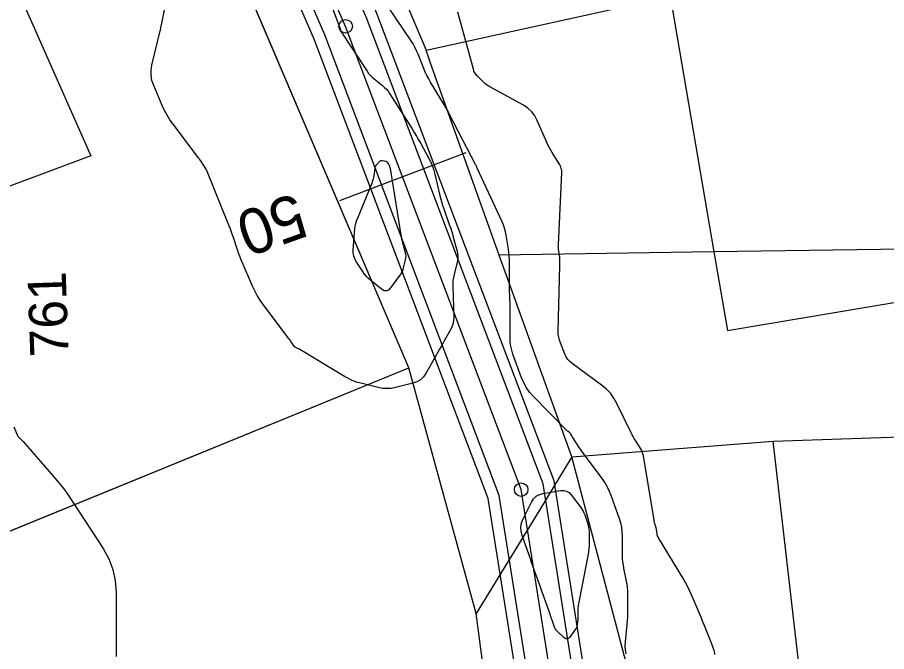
# Model space of a CAD drawing. Extents: x -534481 to -534256, y -1190577 to -1190138.
# Drawn here: x -534403.93 to -534384.66, y -1190491.61 to -1190477.55 of the extents above; entities that cross this region are included whole.
import ezdxf

# ---------------------------------------------------------------- set-up
doc = ezdxf.new("R2010")
doc.units = 0
for name, color, linetype in [('0_kroužky', 7, 'Continuous'), ('30', 7, 'Continuous'), ('31', 7, 'Continuous'), ('_N_osa', 7, 'Continuous'), ('_N_text', 7, 'Continuous'), ('_tenka', 7, 'Continuous'), ('Hranice parcel', 7, 'Continuous'), ('Parcelní čísla', 7, 'Continuous'), ('Polygon budovy', 7, 'Continuous')]:
    doc.layers.add(name, color=color, linetype=linetype)

msp = doc.modelspace()

# ---------------------------------------------------------------- linework, layer by layer
at = {"layer": '0_kroužky'}
for centre in [(-534396.655, -1190477.752), (-534396.655, -1190477.752), (-534396.655, -1190477.752), (-534396.655, -1190477.752), (-534396.655, -1190477.752), (-534396.655, -1190477.752), (-534392.763, -1190488.017), (-534392.763, -1190488.017), (-534392.763, -1190488.017), (-534392.763, -1190488.017), (-534392.763, -1190488.017), (-534392.763, -1190488.017)]:
    msp.add_circle(centre, 0.15, dxfattribs=at)
at = {"layer": '30'}
for points in [[(-534390.433, -1190491.658), (-534390.451, -1190491.57), (-534390.457, -1190491.482), (-534390.453, -1190491.391), (-534390.414, -1190491.008), (-534390.406, -1190490.926), (-534390.401, -1190490.844), (-534390.398, -1190490.762), (-534390.398, -1190490.68), (-534390.4, -1190490.333), (-534390.402, -1190490.26), (-534390.407, -1190490.188), (-534390.417, -1190490.116), (-534390.429, -1190490.045), (-534390.487, -1190489.759), (-534390.499, -1190489.688), (-534390.508, -1190489.616), (-534390.514, -1190489.544), (-534390.516, -1190489.471), (-534390.518, -1190489.038), (-534390.522, -1190488.942), (-534390.534, -1190488.847), (-534390.555, -1190488.754), (-534390.583, -1190488.663), (-534390.76, -1190488.167), (-534390.804, -1190488.057), (-534390.856, -1190487.95), (-534390.916, -1190487.848), (-534390.984, -1190487.75), (-534391.37, -1190487.236), (-534391.398, -1190487.198), (-534391.426, -1190487.16), (-534391.452, -1190487.121), (-534391.478, -1190487.082), (-534391.621, -1190486.862), (-534391.626, -1190486.853), (-534391.632, -1190486.844), (-534391.636, -1190486.835), (-534391.641, -1190486.826), (-534391.659, -1190486.788), (-534391.664, -1190486.779), (-534391.67, -1190486.771), (-534391.677, -1190486.764), (-534391.685, -1190486.757), (-534391.724, -1190486.729), (-534391.734, -1190486.722), (-534391.742, -1190486.714), (-534391.751, -1190486.707), (-534391.759, -1190486.699), (-534392.498, -1190485.948), (-534392.579, -1190485.857), (-534392.649, -1190485.758), (-534392.708, -1190485.653), (-534392.755, -1190485.54), (-534392.946, -1190485.017), (-534392.973, -1190484.93), (-534392.993, -1190484.842), (-534393.005, -1190484.752), (-534393.009, -1190484.661), (-534393.009, -1190484.246), (-534393.009, -1190484.178), (-534393.009, -1190484.11), (-534393.01, -1190484.042), (-534393.011, -1190483.974), (-534393.017, -1190483.703), (-534393.019, -1190483.635), (-534393.02, -1190483.567), (-534393.02, -1190483.499), (-534393.02, -1190483.432), (-534393.02, -1190483.002), (-534393.022, -1190482.923), (-534393.027, -1190482.845), (-534393.034, -1190482.767), (-534393.046, -1190482.689), (-534393.097, -1190482.379), (-534393.112, -1190482.302), (-534393.133, -1190482.227), (-534393.158, -1190482.153), (-534393.188, -1190482.081), (-534393.739, -1190480.892), (-534393.743, -1190480.882), (-534393.746, -1190480.873), (-534393.753, -1190480.852), (-534393.756, -1190480.845), (-534393.759, -1190480.838), (-534393.77, -1190480.818), (-534393.773, -1190480.811), (-534394.342, -1190479.717), (-534394.389, -1190479.627), (-534394.438, -1190479.538), (-534394.489, -1190479.45), (-534394.541, -1190479.363), (-534394.77, -1190478.99), (-534394.813, -1190478.916), (-534394.853, -1190478.841), (-534394.889, -1190478.765), (-534394.922, -1190478.686), (-534395.047, -1190478.37), (-534395.081, -1190478.292), (-534395.118, -1190478.216), (-534395.16, -1190478.142), (-534395.205, -1190478.07), (-534395.7, -1190477.339)], [(-534404.007, -1190486.624), (-534403.927, -1190486.816), (-534403.921, -1190486.83), (-534403.913, -1190486.842), (-534403.904, -1190486.854), (-534403.893, -1190486.865), (-534403.847, -1190486.905), (-534403.835, -1190486.915), (-534403.824, -1190486.926), (-534403.814, -1190486.937), (-534403.803, -1190486.948), (-534403.126, -1190487.727), (-534403.012, -1190487.863), (-534402.903, -1190488.002), (-534402.799, -1190488.145), (-534402.7, -1190488.292), (-534402.031, -1190489.324), (-534401.905, -1190489.551), (-534401.815, -1190489.788), (-534401.761, -1190490.036), (-534401.743, -1190490.295), (-534401.743, -1190491.711)]]:
    msp.add_lwpolyline(points, dxfattribs=at)
msp.add_lwpolyline([(-534395.702, -1190483.595), (-534395.75, -1190483.615), (-534395.802, -1190483.609), (-534395.857, -1190483.576), (-534396.094, -1190483.386), (-534396.145, -1190483.342), (-534396.192, -1190483.294), (-534396.235, -1190483.242), (-534396.274, -1190483.187), (-534396.421, -1190482.959), (-534396.453, -1190482.9), (-534396.474, -1190482.839), (-534396.485, -1190482.775), (-534396.486, -1190482.709), (-534396.459, -1190482.317), (-534396.45, -1190482.229), (-534396.433, -1190482.144), (-534396.41, -1190482.06), (-534396.38, -1190481.977), (-534396.061, -1190481.202), (-534396.048, -1190481.168), (-534396.038, -1190481.133), (-534396.029, -1190481.098), (-534396.023, -1190481.062), (-534396.001, -1190480.889), (-534395.996, -1190480.867), (-534395.988, -1190480.848), (-534395.978, -1190480.829), (-534395.964, -1190480.813), (-534395.893, -1190480.741), (-534395.881, -1190480.731), (-534395.868, -1190480.725), (-534395.854, -1190480.722), (-534395.838, -1190480.724), (-534395.761, -1190480.739), (-534395.753, -1190480.741), (-534395.745, -1190480.745), (-534395.739, -1190480.751), (-534395.733, -1190480.758), (-534395.709, -1190480.795), (-534395.704, -1190480.805), (-534395.698, -1190480.815), (-534395.687, -1190480.835), (-534395.685, -1190480.84), (-534395.682, -1190480.845), (-534395.68, -1190480.85), (-534395.679, -1190480.856), (-534395.668, -1190480.905), (-534395.665, -1190480.915), (-534395.663, -1190480.925), (-534395.661, -1190480.935), (-534395.66, -1190480.945), (-534395.42, -1190482.421), (-534395.413, -1190482.464), (-534395.404, -1190482.507), (-534395.394, -1190482.55), (-534395.382, -1190482.592), (-534395.335, -1190482.76), (-534395.326, -1190482.802), (-534395.322, -1190482.845), (-534395.325, -1190482.887), (-534395.332, -1190482.929), (-534395.376, -1190483.103), (-534395.389, -1190483.146), (-534395.405, -1190483.186), (-534395.426, -1190483.225), (-534395.45, -1190483.262), (-534395.657, -1190483.549)], close=True, dxfattribs=at)
at = {"layer": '31'}
for points in [[(-534397.096, -1190476.95), (-534396.777, -1190477.804), (-534396.774, -1190477.81), (-534396.773, -1190477.816), (-534396.771, -1190477.821), (-534396.77, -1190477.828), (-534396.765, -1190477.852), (-534396.763, -1190477.858), (-534396.761, -1190477.863), (-534396.759, -1190477.869), (-534396.756, -1190477.874), (-534396.178, -1190478.746), (-534396.144, -1190478.794), (-534396.106, -1190478.838), (-534396.065, -1190478.88), (-534396.021, -1190478.918), (-534395.836, -1190479.065), (-534395.791, -1190479.104), (-534395.75, -1190479.145), (-534395.713, -1190479.19), (-534395.68, -1190479.239), (-534395.181, -1190480.022), (-534395.132, -1190480.102), (-534395.083, -1190480.183), (-534395.036, -1190480.265), (-534394.99, -1190480.347), (-534394.809, -1190480.679), (-534394.767, -1190480.763), (-534394.73, -1190480.849), (-534394.7, -1190480.938), (-534394.675, -1190481.028), (-534394.572, -1190481.469), (-534394.552, -1190481.552), (-534394.529, -1190481.634), (-534394.504, -1190481.715), (-534394.477, -1190481.796), (-534394.357, -1190482.14), (-534394.333, -1190482.21), (-534394.311, -1190482.28), (-534394.289, -1190482.35), (-534394.269, -1190482.42), (-534394.187, -1190482.71), (-534394.173, -1190482.777), (-534394.167, -1190482.845), (-534394.171, -1190482.912), (-534394.183, -1190482.98), (-534394.251, -1190483.251), (-534394.266, -1190483.319), (-534394.275, -1190483.387), (-534394.28, -1190483.456), (-534394.281, -1190483.526), (-534394.259, -1190484.187), (-534394.262, -1190484.259), (-534394.274, -1190484.328), (-534394.295, -1190484.396), (-534394.326, -1190484.461), (-534394.468, -1190484.717), (-534394.503, -1190484.781), (-534394.539, -1190484.844), (-534394.575, -1190484.908), (-534394.611, -1190484.972), (-534394.876, -1190485.441), (-534394.931, -1190485.52), (-534394.998, -1190485.582), (-534395.076, -1190485.63), (-534395.166, -1190485.661), (-534395.551, -1190485.756), (-534395.647, -1190485.774), (-534395.743, -1190485.78), (-534395.839, -1190485.774), (-534395.935, -1190485.756), (-534396.319, -1190485.66), (-534396.414, -1190485.633), (-534396.506, -1190485.599), (-534396.594, -1190485.558), (-534396.681, -1190485.51), (-534397.67, -1190484.912), (-534397.677, -1190484.908), (-534397.684, -1190484.904), (-534397.691, -1190484.901), (-534397.699, -1190484.897), (-534397.738, -1190484.88), (-534397.746, -1190484.876), (-534397.759, -1190484.869), (-534397.764, -1190484.865), (-534397.769, -1190484.862), (-534397.784, -1190484.85), (-534397.787, -1190484.847), (-534397.789, -1190484.844), (-534397.792, -1190484.841), (-534397.795, -1190484.838), (-534397.866, -1190484.734), (-534397.878, -1190484.715), (-534397.891, -1190484.697), (-534397.905, -1190484.679), (-534397.918, -1190484.661), (-534398.48, -1190483.918), (-534398.549, -1190483.82), (-534398.612, -1190483.719), (-534398.669, -1190483.614), (-534398.72, -1190483.506), (-534398.946, -1190482.979), (-534398.974, -1190482.911), (-534399.001, -1190482.843), (-534399.026, -1190482.775), (-534399.05, -1190482.706), (-534399.143, -1190482.429), (-534399.167, -1190482.36), (-534399.191, -1190482.291), (-534399.217, -1190482.223), (-534399.244, -1190482.155), (-534399.738, -1190480.933), (-534399.741, -1190480.927), (-534399.744, -1190480.921), (-534399.747, -1190480.915), (-534399.75, -1190480.909), (-534399.774, -1190480.87), (-534399.787, -1190480.848), (-534399.794, -1190480.838), (-534399.865, -1190480.734), (-534399.878, -1190480.716), (-534399.89, -1190480.698), (-534399.904, -1190480.68), (-534399.917, -1190480.662), (-534400.48, -1190479.918), (-534400.549, -1190479.82), (-534400.612, -1190479.719), (-534400.669, -1190479.614), (-534400.72, -1190479.506), (-534400.909, -1190479.065), (-534400.947, -1190478.954), (-534400.966, -1190478.841), (-534400.966, -1190478.727), (-534400.947, -1190478.611), (-534400.771, -1190477.88), (-534400.769, -1190477.87), (-534400.766, -1190477.86), (-534400.76, -1190477.841), (-534400.757, -1190477.831), (-534400.755, -1190477.821), (-534400.589, -1190476.994)], [(-534388.464, -1190491.668), (-534388.488, -1190491.585), (-534388.515, -1190491.502), (-534388.546, -1190491.421), (-534388.708, -1190491.015), (-534388.742, -1190490.93), (-534388.777, -1190490.845), (-534388.813, -1190490.76), (-534388.849, -1190490.675), (-534388.994, -1190490.337), (-534389.031, -1190490.253), (-534389.072, -1190490.17), (-534389.115, -1190490.089), (-534389.161, -1190490.01), (-534389.717, -1190489.087), (-534389.729, -1190489.065), (-534389.739, -1190489.042), (-534389.746, -1190489.018), (-534389.751, -1190488.994), (-534389.774, -1190488.858), (-534389.776, -1190488.851), (-534389.777, -1190488.845), (-534389.779, -1190488.838), (-534389.781, -1190488.831), (-534389.791, -1190488.805), (-534389.793, -1190488.799), (-534389.795, -1190488.792), (-534389.796, -1190488.786), (-534389.798, -1190488.779), (-534390.054, -1190487.268), (-534390.065, -1190487.221), (-534390.08, -1190487.176), (-534390.1, -1190487.132), (-534390.124, -1190487.09), (-534390.23, -1190486.926), (-534390.256, -1190486.885), (-534390.281, -1190486.843), (-534390.304, -1190486.8), (-534390.326, -1190486.757), (-534390.64, -1190486.106), (-534390.706, -1190485.989), (-534390.784, -1190485.882), (-534390.876, -1190485.785), (-534390.98, -1190485.699), (-534391.634, -1190485.223), (-534391.685, -1190485.18), (-534391.728, -1190485.132), (-534391.765, -1190485.078), (-534391.794, -1190485.018), (-534391.895, -1190484.768), (-534391.917, -1190484.704), (-534391.932, -1190484.64), (-534391.94, -1190484.574), (-534391.942, -1190484.507), (-534391.91, -1190483.052), (-534391.909, -1190483.031), (-534391.909, -1190483.01), (-534391.909, -1190482.99), (-534391.909, -1190482.969), (-534391.909, -1190482.886), (-534391.909, -1190482.865), (-534391.911, -1190482.845), (-534391.913, -1190482.824), (-534391.916, -1190482.804), (-534391.933, -1190482.696), (-534391.937, -1190482.671), (-534391.939, -1190482.646), (-534391.94, -1190482.621), (-534391.939, -1190482.596), (-534391.861, -1190480.991), (-534391.861, -1190480.976), (-534391.862, -1190480.961), (-534391.864, -1190480.947), (-534391.868, -1190480.932), (-534391.884, -1190480.874), (-534391.889, -1190480.859), (-534391.894, -1190480.845), (-534391.901, -1190480.832), (-534391.908, -1190480.819), (-534392.079, -1190480.546), (-534392.109, -1190480.496), (-534392.137, -1190480.445), (-534392.164, -1190480.392), (-534392.188, -1190480.339), (-534392.417, -1190479.82), (-534392.47, -1190479.722), (-534392.536, -1190479.636), (-534392.616, -1190479.562), (-534392.71, -1190479.501), (-534393.456, -1190479.094), (-534393.496, -1190479.071), (-534393.534, -1190479.045), (-534393.569, -1190479.016), (-534393.603, -1190478.985), (-534393.734, -1190478.854), (-534393.764, -1190478.82), (-534393.789, -1190478.783), (-534393.809, -1190478.743), (-534393.823, -1190478.7), (-534394.17, -1190477.437)]]:
    msp.add_lwpolyline(points, dxfattribs=at)
msp.add_lwpolyline([(-534391.717, -1190491.319), (-534391.746, -1190491.331), (-534391.777, -1190491.325), (-534391.81, -1190491.302), (-534391.96, -1190491.161), (-534391.984, -1190491.135), (-534392.004, -1190491.108), (-534392.02, -1190491.078), (-534392.033, -1190491.045), (-534392.078, -1190490.911), (-534392.089, -1190490.878), (-534392.1, -1190490.845), (-534392.112, -1190490.811), (-534392.123, -1190490.778), (-534392.247, -1190490.43), (-534392.271, -1190490.361), (-534392.296, -1190490.292), (-534392.32, -1190490.223), (-534392.345, -1190490.154), (-534392.472, -1190489.797), (-534392.502, -1190489.715), (-534392.531, -1190489.633), (-534392.56, -1190489.55), (-534392.589, -1190489.467), (-534392.742, -1190489.032), (-534392.765, -1190488.939), (-534392.769, -1190488.847), (-534392.754, -1190488.756), (-534392.719, -1190488.666), (-534392.536, -1190488.294), (-534392.489, -1190488.221), (-534392.431, -1190488.165), (-534392.36, -1190488.126), (-534392.277, -1190488.103), (-534391.889, -1190488.038), (-534391.82, -1190488.035), (-534391.757, -1190488.05), (-534391.702, -1190488.082), (-534391.654, -1190488.133), (-534391.444, -1190488.413), (-534391.417, -1190488.451), (-534391.393, -1190488.492), (-534391.373, -1190488.534), (-534391.355, -1190488.577), (-534391.292, -1190488.755), (-534391.278, -1190488.8), (-534391.268, -1190488.846), (-534391.262, -1190488.892), (-534391.26, -1190488.939), (-534391.259, -1190489.208), (-534391.26, -1190489.269), (-534391.264, -1190489.329), (-534391.271, -1190489.389), (-534391.281, -1190489.449), (-534391.494, -1190490.548), (-534391.499, -1190490.577), (-534391.502, -1190490.607), (-534391.504, -1190490.636), (-534391.505, -1190490.666), (-534391.504, -1190490.79), (-534391.504, -1190490.817), (-534391.505, -1190490.844), (-534391.507, -1190490.872), (-534391.509, -1190490.899), (-534391.521, -1190491.007), (-534391.525, -1190491.034), (-534391.533, -1190491.059), (-534391.544, -1190491.083), (-534391.558, -1190491.106), (-534391.69, -1190491.29)], close=True, dxfattribs=at)
at = {"layer": '_N_osa'}
msp.add_lwpolyline([(-534408.105, -1190518.46), (-534393.616, -1190502.389), (-534391.346, -1190496.962), (-534392.763, -1190488.017), (-534396.655, -1190477.752), (-534402.513, -1190464.283), (-534404.757, -1190456.741), (-534408.311, -1190433.088), (-534409.248, -1190427.879), (-534409.316, -1190416.054), (-534409.076, -1190409.418), (-534409.868, -1190391.439)], dxfattribs=at)
at = {"layer": '_N_text'}
for p, q in [((-534393.987, -1190480.557), (-534396.792, -1190481.62)), ((-534394.864, -1190483.098), (-534394.864, -1190483.098))]:
    msp.add_line(p, q, dxfattribs=at)
at = {"layer": '_tenka'}
for points in [[(-534405.407, -1190514.348), (-534394.258, -1190501.982), (-534392.12, -1190496.869), (-534393.492, -1190488.211), (-534397.35, -1190478.035), (-534403.219, -1190464.54), (-534405.491, -1190456.905), (-534409.051, -1190433.21), (-534409.998, -1190427.948), (-534410.066, -1190416.042), (-534409.827, -1190409.421), (-534410.645, -1190390.84)], [(-534405.057, -1190514.333), (-534394.044, -1190502.118), (-534391.862, -1190496.9), (-534393.249, -1190488.146), (-534397.118, -1190477.94), (-534402.983, -1190464.455), (-534405.247, -1190456.85), (-534408.804, -1190433.17), (-534409.748, -1190427.925), (-534409.816, -1190416.046), (-534409.577, -1190409.42), (-534410.397, -1190390.795)], [(-534403.656, -1190514.273), (-534393.187, -1190502.661), (-534390.83, -1190497.024), (-534392.278, -1190487.888), (-534396.191, -1190477.563), (-534402.042, -1190464.111), (-534404.268, -1190456.632), (-534407.818, -1190433.007), (-534408.749, -1190427.833), (-534408.816, -1190416.061), (-534408.576, -1190409.416), (-534409.363, -1190391.537)], [(-534403.306, -1190514.257), (-534392.973, -1190502.796), (-534390.572, -1190497.055), (-534392.035, -1190487.824), (-534395.96, -1190477.469), (-534401.807, -1190464.025), (-534404.023, -1190456.578), (-534407.571, -1190432.966), (-534408.499, -1190427.81), (-534408.566, -1190416.065), (-534408.326, -1190409.415), (-534409.111, -1190391.586)]]:
    msp.add_lwpolyline(points, dxfattribs=at)
at = {"layer": 'Hranice parcel'}
for p, q in [((-534397.97, -1190470.9), (-534394.87, -1190478.28)), ((-534395.25, -1190485.32), (-534400.89, -1190472.11)), ((-534394.77, -1190478.57), (-534394.87, -1190478.28)), ((-534393.25, -1190482.82), (-534394.77, -1190478.57)), ((-534391.64, -1190487.29), (-534393.25, -1190482.82)), ((-534408.72, -1190490.82), (-534395.25, -1190485.32)), ((-534393.76, -1190490.76), (-534395.25, -1190485.32)), ((-534391.64, -1190487.29), (-534387.18, -1190486.94))]:
    msp.add_line(p, q, dxfattribs=at)
for points in [[(-534394.87, -1190478.28), (-534389.45, -1190477.08), (-534382.56, -1190476.12), (-534376.75, -1190475.31)], [(-534377.4, -1190482.59), (-534388.49, -1190482.75), (-534393.25, -1190482.82)], [(-534387.18, -1190486.94), (-534381.11, -1190486.74), (-534380.38, -1190486.72), (-534376.48, -1190486.28)], [(-534385.13, -1190504.81), (-534385.97, -1190497.46), (-534387.18, -1190486.94)], [(-534391.64, -1190487.29), (-534392.36, -1190488.47), (-534393.76, -1190490.76)], [(-534389.82, -1190497.69), (-534389.73, -1190494.54), (-534391.64, -1190487.29)], [(-534393.4, -1190496.16), (-534393.44, -1190493.16), (-534393.76, -1190490.76)]]:
    msp.add_lwpolyline(points, dxfattribs=at)
at = {"layer": 'Polygon budovy'}
for points in [[(-534413.98, -1190478.05), (-534410.74, -1190485.76), (-534408.96, -1190490.21), (-534408.72, -1190490.82), (-534395.25, -1190485.32), (-534400.89, -1190472.11), (-534405.17, -1190474.16), (-534402.3, -1190480.62), (-534406.62, -1190482.23), (-534409.2, -1190476.06), (-534410.27, -1190476.57)], [(-534389.45, -1190477.08), (-534389.41, -1190477.39), (-534388.49, -1190482.75), (-534388.19, -1190484.49), (-534381.78, -1190483.41), (-534381.11, -1190486.74), (-534380.38, -1190486.72), (-534376.48, -1190486.28), (-534376.96, -1190484.36), (-534377.4, -1190482.59), (-534375.83, -1190482.13), (-534376.75, -1190475.31), (-534382.56, -1190476.12)]]:
    msp.add_lwpolyline(points, close=True, dxfattribs=at)

# ---------------------------------------------------------------- texts
at = {"layer": '_N_text'}
msp.add_text('50', height=1, rotation=199.5335, dxfattribs=at).set_placement((-534397.754, -1190481.43))
at = {"layer": 'Parcelní čísla'}
msp.add_text('761', height=0.85, rotation=92, dxfattribs=at).set_placement((-534402.793, -1190485.067))

doc.saveas('drawing.dxf')
